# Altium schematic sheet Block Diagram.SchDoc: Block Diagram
size 431 x 279 mm; Date: Not shown in title block; ApprovedBy: Not shown in title block; CheckedBy: Not shown in title block; Author: Not shown in title block; CompanyName: Not shown in title block; Engineer: Not shown in title block; Organization: Not shown in title block; Address1: Not shown in title block; Address2: Not shown in title block; Address3: Not shown in title block; Address4: Not shown in title block; DocumentNumber: 1; Revision: Use project parameter SCH_Rev; SheetNumber: 1; SheetTotal: 15; PageSetup: Record=PageOptions¦CenterHorizontal=True¦CenterVertical=True¦PrintScale=1.00¦XCorrection=1.00¦YCorrection=1.00¦PrintKind=0¦BorderSize=5000000¦LeftOffset=0¦BottomOffset=0¦Orientation=2¦PaperLength=1000¦PaperWidth=1000¦Scale=100¦PaperSource=15¦PrintQuality=600¦MediaType=1¦DitherType=10¦PaperKind=Letter¦PrintScaleMode=1
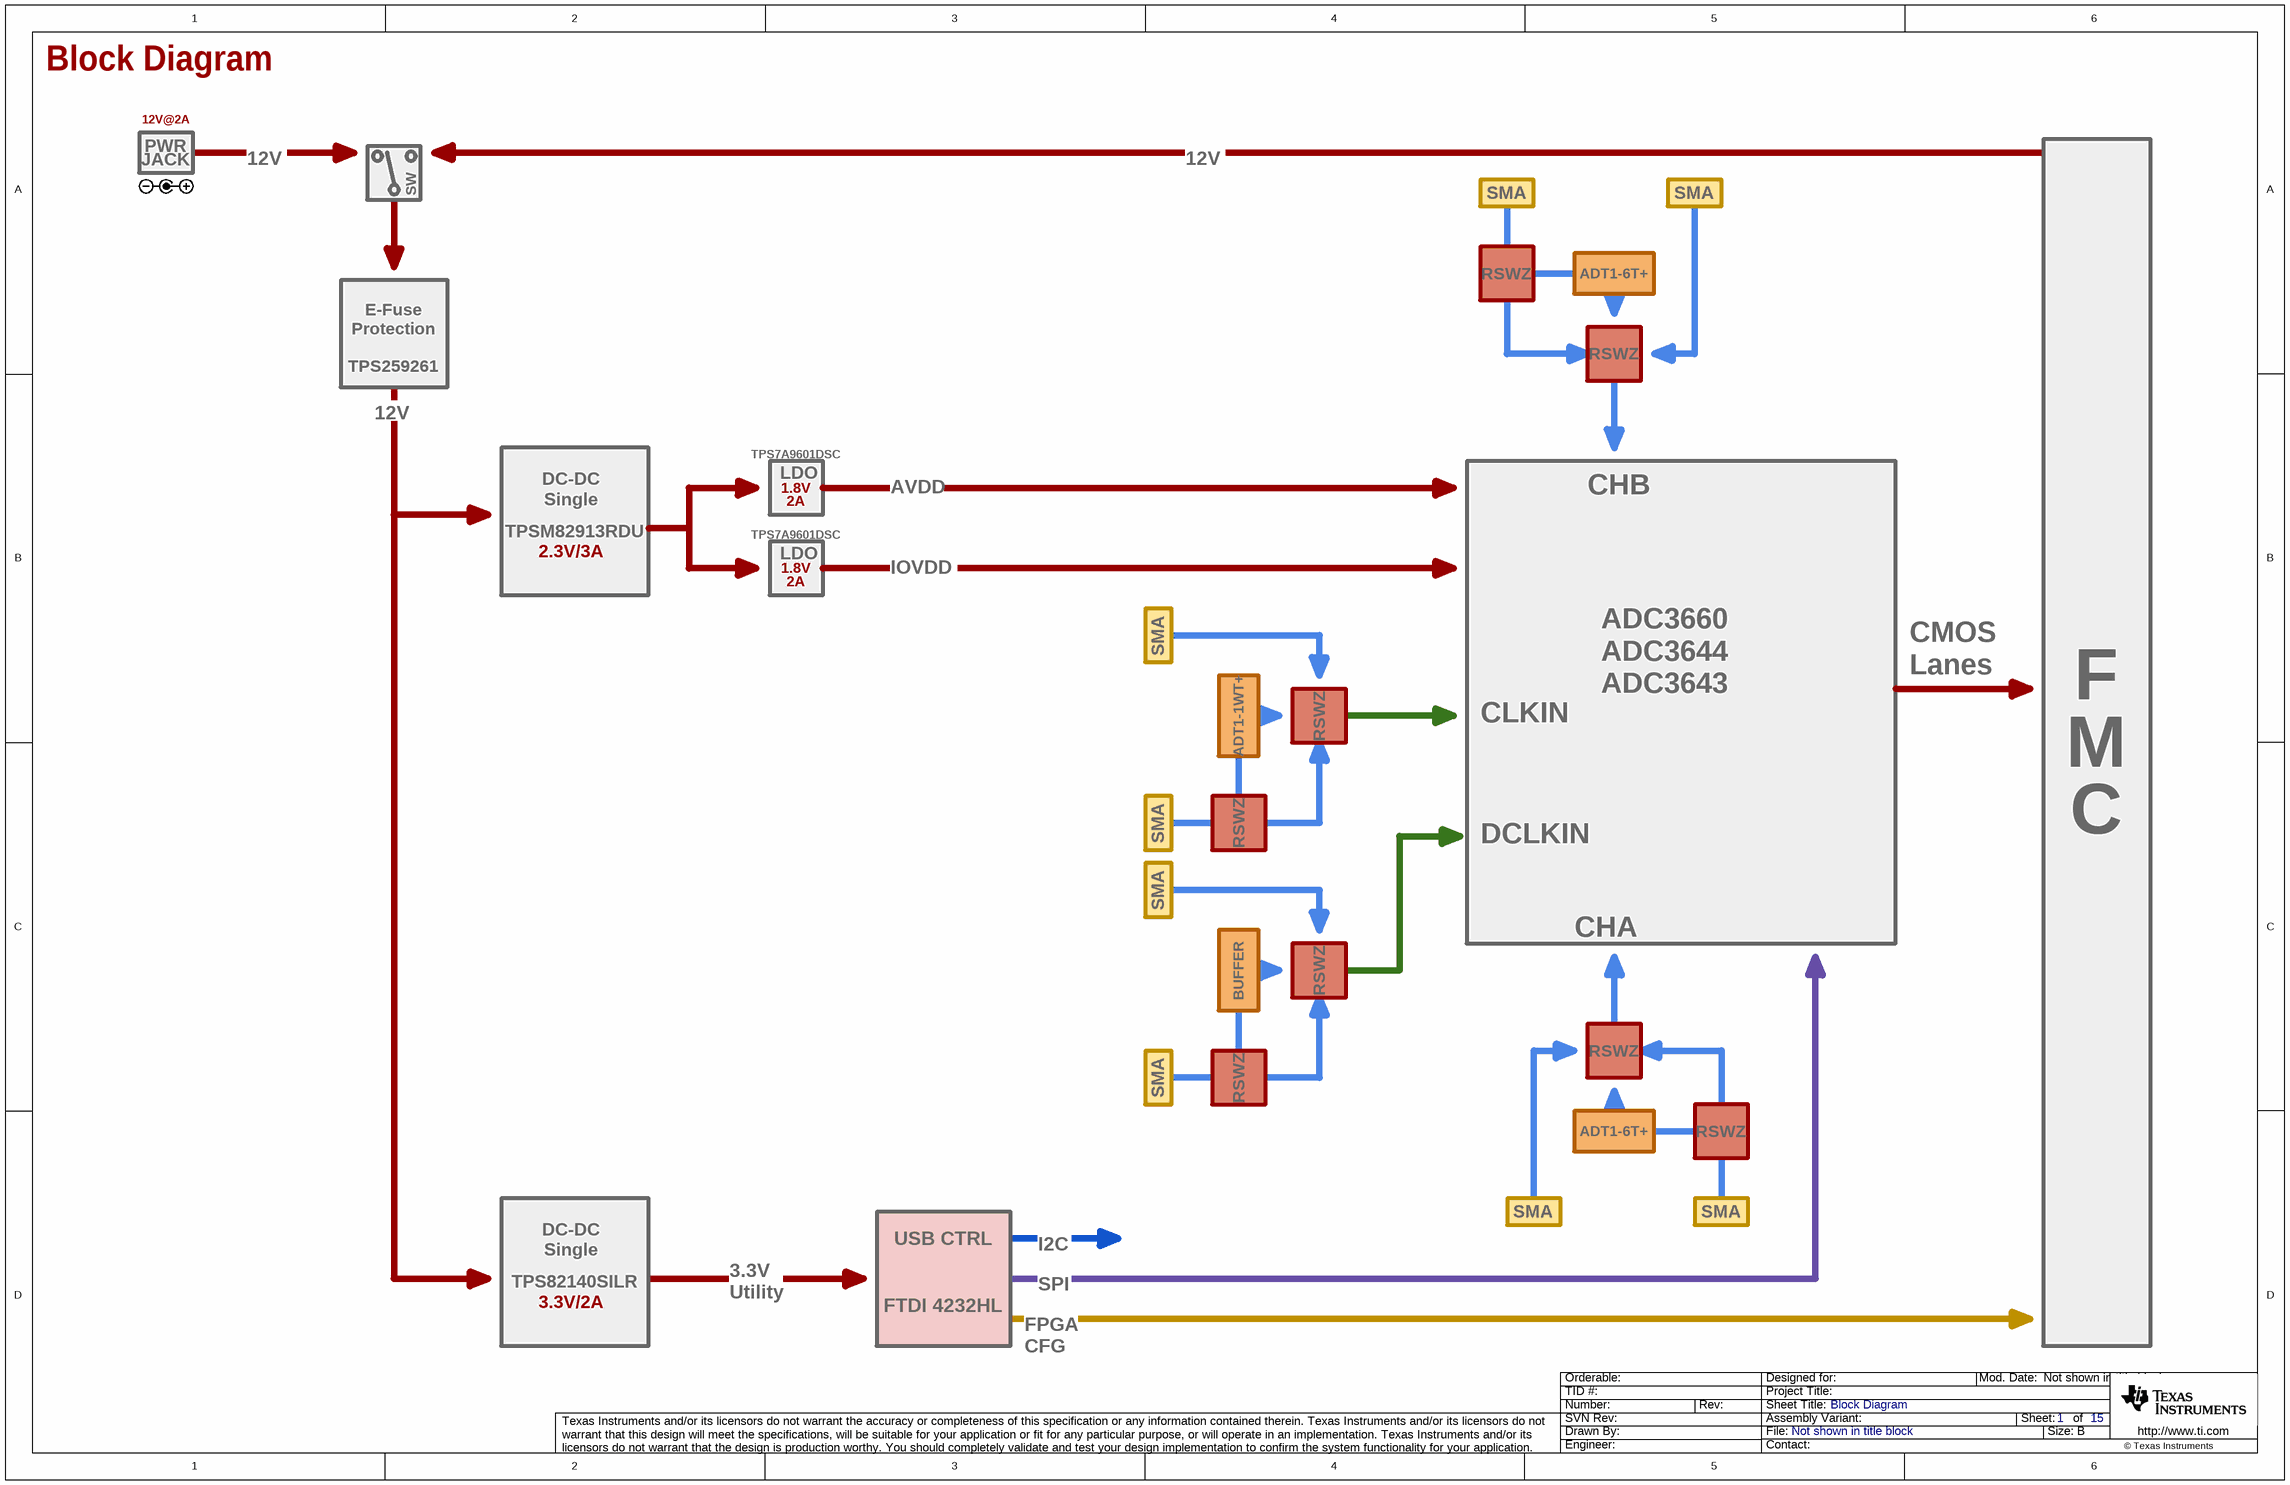
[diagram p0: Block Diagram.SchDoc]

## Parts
(Parts that share a designator on the sheet are numbered #1, #2 ... from top to bottom, then left to right.)
*#1  SMA  (graphical)
*#2  SMA  (graphical)
*#3  PartNum: RSWZ  (hidden comment: R-SWIZZLE)  (graphical)
*#4  PartNum: ADT1-6T+  (hidden comment: Balun)  (graphical)
*#5  PartNum: RSWZ  (hidden comment: R-SWIZZLE)  (graphical)
*#6  A_Value: 2A  V_Value: 1.8V  PartNum: TPS7A9601DSC  (hidden comment: LDO)  (graphical)
*#7  Limits: 2.3V/3A  PartNum: TPSM82913RDU  (hidden comment: DC-DC Single)  (graphical)
*#8  A_Value: 2A  V_Value: 1.8V  PartNum: TPS7A9601DSC  (hidden comment: LDO)  (graphical)
*#9  SMA  (graphical)
*#10  PartNum: ADT1-1WT+  (hidden comment: Balun)  (graphical)
*#11  PartNum: RSWZ  (hidden comment: R-SWIZZLE)  (graphical)
*#12  FMC  (value not drawn)  (graphical)
*#13  SMA  (graphical)
*#14  PartNum: RSWZ  (hidden comment: R-SWIZZLE)  (graphical)
*#15  SMA  (graphical)
*#16  PartNum: BUFFER  (hidden comment: Balun)  (graphical)
*#17  PartNum: RSWZ  (hidden comment: R-SWIZZLE)  (graphical)
*#18  PartNum: RSWZ  (hidden comment: R-SWIZZLE)  (graphical)
*#19  SMA  (graphical)
*#20  PartNum: RSWZ  (hidden comment: R-SWIZZLE)  (graphical)
*#21  PartNum: ADT1-6T+  (hidden comment: Balun)  (graphical)
*#22  PartNum: RSWZ  (hidden comment: R-SWIZZLE)  (graphical)
*#23  SMA  (graphical)
*#24  SMA  (graphical)
*#25  Limits: 3.3V/2A  PartNum: TPS82140SILR  (hidden comment: DC-DC Single)  (graphical)
*#26  FTDI 4232HL  (value not drawn)  (graphical)
*?#1  PartNum: 12V@2A  (hidden comment: Power Jack)  (graphical)
*?#2  SWITCH  (value not drawn)  (graphical)
*?#3  E-Fuse  (value not drawn)  (graphical)

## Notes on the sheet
- 12V
- AVDD
- CHB
- IOVDD
- ADC3660
  ADC3644
  ADC3643
- CLKIN
- CMOS Lanes
- DCLKIN
- CHA
- 3.3V
  Utility
- I2C
- SPI
- FPGA
  CFG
